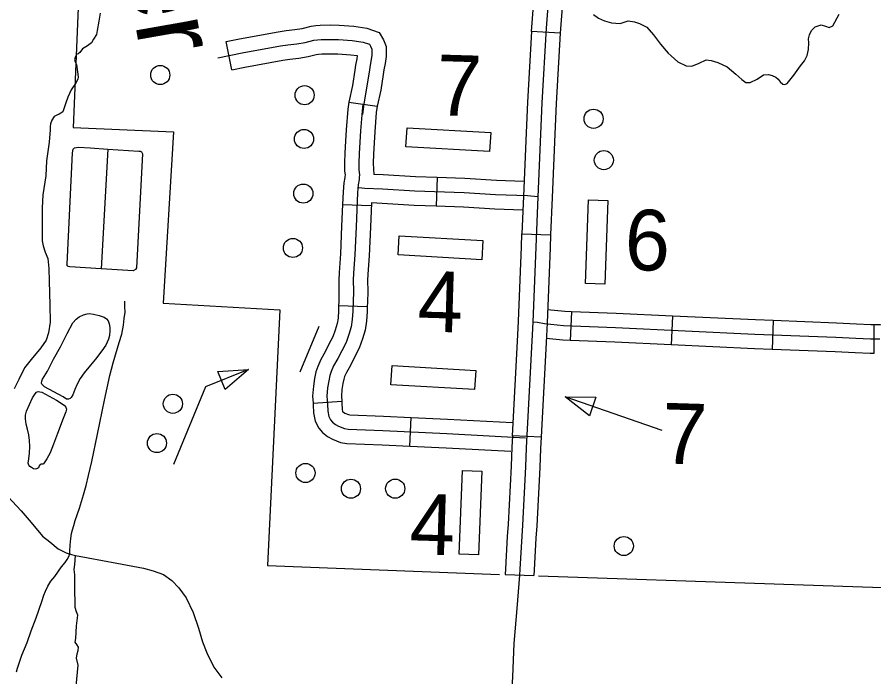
# Model space of a CAD drawing. Extents: x 653372 to 905732, y 627442 to 787275.
# Drawn here: x 690649 to 695124, y 780092 to 783537 of the extents above; entities that cross this region are included whole.
import ezdxf

# ---------------------------------------------------------------- set-up
doc = ezdxf.new("R2010")
doc.units = 0
for name, color, linetype in [('31', 7, 'Continuous'), ('32', 7, 'Continuous'), ('33', 7, 'Continuous'), ('34', 7, 'Continuous'), ('35', 7, 'Continuous'), ('45', 7, 'Continuous'), ('56', 7, 'Continuous'), ('6', 7, 'Continuous')]:
    doc.layers.add(name, color=color, linetype=linetype)

msp = doc.modelspace()

# ---------------------------------------------------------------- linework, layer by layer
at = {"layer": '31'}
for p, q in [((693485.5, 783452.3), (693335.8, 783461.2)), ((693285.4, 782404.8), (693435.3, 782399.2)), ((693435.3, 782399.2), (693435.3, 782399.2)), ((693385.4, 781343.3), (693235.6, 781351.1))]:
    msp.add_line(p, q, dxfattribs=at)
for points in [[(693335.8, 783461.2), (693337.2, 783484.8), (693345.3, 783596.8), (693348.1, 783659.5), (693349.8, 783717.8), (693358.7, 783986.7)], [(693508.6, 783981.7), (693499.8, 783713.1), (693498, 783653.9), (693495, 783588), (693486.9, 783475), (693485.5, 783452.3)], [(693420.2, 783592.4), (693412, 783479.9), (693388.9, 783088.9), (693367.8, 782598.5), (693357.8, 782334.8), (693341.8, 781944.7), (693307.4, 781288.1), (693303.4, 781188.1), (693287.7, 780884.5), (693274, 780653.3), (693273.2, 780623.2)], [(693335.8, 783461.2), (693314, 783092.8), (693307.1, 782932.8)], [(693485.5, 783452.3), (693463.8, 783085.1), (693457, 782926.3)], [(693307.1, 782932.8), (693292.8, 782601.5), (693285.4, 782404.8)], [(693457, 782926.3), (693442.7, 782595.4), (693435.3, 782399.2)], [(693263.2, 781878.4), (693266.9, 781948.2), (693282.8, 782337.8), (693285.4, 782404.8)], [(693435.3, 782399.2), (693432.7, 782331.9), (693416.7, 781941.2), (693413, 781870.5)], [(693235.6, 781351.1), (693263.2, 781878.4)], [(693413, 781870.5), (693385.4, 781343.3)], [(693235.6, 781351.1), (693232.5, 781291.5), (693228.5, 781191.5), (693212.8, 780888.6), (693209, 780824.3)], [(693385.4, 781343.3), (693382.3, 781284.6), (693378.4, 781184.7), (693362.6, 780880.3), (693358.7, 780815.4)], [(693209, 780824.3), (693199.1, 780656.6), (693198.2, 780625.8), (693348.1, 780620.5)], [(693358.7, 780815.4), (693349, 780650), (693348.1, 780620.5)]]:
    msp.add_lwpolyline(points, dxfattribs=at)
at = {"layer": '32'}
for p, q in [((692380.7, 783092), (692529.2, 783071)), ((692842.9, 782699.4), (692838.1, 782549.5)), ((692348.4, 782558.3), (692498.2, 782552.2)), ((692327.5, 782030.1), (692477.4, 782025.6)), ((693543.8, 781998.5), (693537.8, 781848.6)), ((694071.8, 781975.4), (694064.8, 781825.6)), ((694598.6, 781951.7), (694592.9, 781801.8)), ((695122.8, 781930.3), (695123.8, 781780.3)), ((692194.2, 781521.3), (692343.9, 781530.7)), ((692700.5, 781296.3), (692707.5, 781446.2))]:
    msp.add_line(p, q, dxfattribs=at)
for points in [[(692380.7, 783092), (692375.5, 783055.7), (692367.4, 782948.3), (692363.7, 782889.1), (692360, 782827.4), (692358.4, 782775.1), (692359.3, 782734.9), (692361.2, 782711.2), (692361, 782704.6), (692360.4, 782699.3), (692355.6, 782671.1), (692351, 782624.4), (692348.4, 782558.3)], [(692454.9, 783081.5), (692450.1, 783047.6), (692442.2, 782943.1), (692438.6, 782884.5), (692434.9, 782824), (692433.4, 782774.8), (692434.2, 782738.8), (692436.3, 782713.1), (692435.9, 782698.9), (692434.6, 782688.6), (692430, 782661.2), (692425.9, 782619.2), (692418.7, 782442.3), (692413.3, 782295.6), (692404.8, 782199.2), (692403.7, 782162.3), (692404.8, 782105.5), (692403.1, 782048.4), (692401.7, 782002), (692399.4, 781957.6), (692393.5, 781919.9), (692381, 781879.5), (692366.4, 781837.3), (692344.3, 781794.7), (692324.1, 781753.6), (692301.2, 781715.5), (692289, 781686.5), (692281.7, 781664.9), (692276.1, 781636.7), (692270.3, 781600.8), (692267.1, 781557.4), (692269.7, 781516.5), (692271.4, 781478.6), (692276.3, 781451.9), (692286.1, 781433.6), (692296.2, 781422), (692311, 781410.2), (692327.8, 781401.1), (692358.6, 781388.8), (692378.4, 781385.4), (692558.5, 781378.1), (692893.3, 781362.4), (693304.5, 781340.5)], [(692529.2, 783071), (692524.7, 783039.5), (692517.1, 782938), (692513.5, 782879.9), (692509.8, 782820.6), (692508.4, 782774.5), (692509.2, 782742.6), (692511.4, 782715.4)], [(692842.9, 782699.4), (692729.7, 782703.1), (692560.3, 782712.9), (692511.4, 782715.4)], [(693296.2, 782678.9), (693151.7, 782684.1), (692987.9, 782694.7), (692842.9, 782699.4)], [(693367.8, 782598.5), (693314.5, 782603.2), (693148, 782609.1), (692984.3, 782619.7), (692726.3, 782628.1), (692556.2, 782638), (692464.5, 782642.6), (692434.3, 782645.8)], [(692348.4, 782558.3), (692343.7, 782445.2), (692338.5, 782300.3), (692329.9, 782203.7), (692328.6, 782162.7), (692329.8, 782105.8), (692328.1, 782050.6), (692327.5, 782030.1)], [(692498.8, 782566.2), (692493.6, 782439.4), (692488.2, 782290.9), (692479.7, 782194.8), (692478.7, 782162), (692479.8, 782105.1), (692478, 782046.1), (692477.4, 782025.6)], [(692838.1, 782549.5), (692723, 782553.2), (692498.8, 782566.2)], [(693290.1, 782529), (693144.2, 782534.2), (692980.6, 782544.8), (692838.1, 782549.5)], [(692327.5, 782030.1), (692326.7, 782005.1), (692324.7, 781965.3), (692320.3, 781936.9), (692309.7, 781902.9), (692297.3, 781866.9), (692277.4, 781828.5), (692258.2, 781789.5), (692234.2, 781749.5), (692218.8, 781713.1), (692209.1, 781684.2), (692202.3, 781649.9), (692195.8, 781609.6), (692191.9, 781557.8), (692194.2, 781521.3)], [(692477.4, 782025.6), (692476.6, 781999), (692474.1, 781949.9), (692466.8, 781902.8), (692452.2, 781856.1), (692435.5, 781807.7), (692411.3, 781760.9), (692390.1, 781717.7), (692368.3, 781681.4), (692359.2, 781659.9), (692354.3, 781645.6), (692350, 781623.4), (692344.9, 781592.1), (692342.3, 781556.9), (692343.9, 781530.7)], [(693543.8, 781998.5), (693508.7, 781999.9), (693419.5, 782008.9)], [(694071.8, 781975.4), (693777.6, 781989.1), (693543.8, 781998.5)], [(694598.6, 781951.7), (694506, 781955.2), (694071.8, 781975.4)], [(694925, 781864.1), (694502.8, 781880.3), (693774.3, 781914.1), (693503.4, 781925.1), (693403.3, 781935.1), (693367, 781942.5), (693341.8, 781944.7)], [(695122.8, 781930.3), (695108.4, 781930.2), (695032.7, 781933.8), (694928.3, 781939.1), (694598.6, 781951.7)], [(695653.2, 781901.9), (695571, 781905), (695462.8, 781910.3), (695289.9, 781922.2), (695156.4, 781930.5), (695122.8, 781930.3)], [(693537.8, 781848.6), (693498.2, 781850.2), (693412.4, 781858.8)], [(694064.8, 781825.6), (693771.1, 781839.2), (693537.8, 781848.6)], [(695154.3, 781855.5), (695106.8, 781855.2), (695029, 781858.9), (694925, 781864.1)], [(694592.9, 781801.8), (694499.6, 781805.4), (694064.8, 781825.6)], [(695123.8, 781780.3), (695105.3, 781780.1), (695025.3, 781784), (694921.6, 781789.2), (694592.9, 781801.8)], [(692194.2, 781521.3), (692194.8, 781512.5), (692196.7, 781470.1), (692204.6, 781426.8), (692224, 781390.8), (692244, 781367.7), (692269.5, 781347.3), (692296, 781333), (692338.1, 781316.3), (692370.5, 781310.7), (692555.2, 781303.2), (692700.5, 781296.3)], [(692343.9, 781530.7), (692344.6, 781520.6), (692346.1, 781487.1), (692347.9, 781477.1), (692348.3, 781476.4), (692348.4, 781476.2), (692352.5, 781473), (692359.5, 781469.2), (692379.2, 781461.4), (692386.4, 781460.1), (692561.8, 781453), (692707.5, 781446.2)], [(692707.5, 781446.2), (692897, 781437.3), (693235.3, 781419.3)], [(692700.5, 781296.3), (692889.5, 781287.5), (693227.4, 781269.5)]]:
    msp.add_lwpolyline(points, dxfattribs=at)
at = {"layer": '33'}
msp.add_lwpolyline([(693273.2, 780623.2), (693259.1, 780449.1), (693242.6, 780266.5), (693236.9, 780092.5), (693228.4, 779975), (693218.4, 779734.2), (693195.3, 779324.1)], dxfattribs=at)
at = {"layer": '34'}
msp.add_lwpolyline([(690644.8, 780117.1), (690650.5, 780136.8), (690658.6, 780162.6), (690672.9, 780204.6), (690700.4, 780271.8), (690722.6, 780331.7), (690748.5, 780400.5), (690777.6, 780486), (690788.2, 780518.5), (690796.8, 780539.2), (690809.5, 780565.5), (690825, 780591.1), (690845, 780616.5), (690879.9, 780665.9), (690899.5, 780689.1), (690909.6, 780704.6), (690918, 780720.2), (690923, 780734.8), (690924, 780748.4), (690926, 780778.9), (690928.2, 780814), (690931.8, 780839.9), (690936.9, 780859.6), (690944.4, 780882.6), (690952, 780907.3), (690974.3, 780972.6), (690995.6, 781041.6), (691008.4, 781091.1), (691021.3, 781144), (691038.8, 781216.1), (691068.6, 781359.7), (691104.2, 781537), (691133, 781664.7), (691150.8, 781731.6), (691181.2, 781837.3), (691196.1, 781881.6), (691204.8, 781927.8), (691208.2, 781963.4), (691212, 781996.7), (691211.1, 782023.9), (691211.4, 782053.3)], dxfattribs=at)
at = {"layer": '35'}
for points in [[(691082.7, 783556.9), (691075.6, 783515.7), (691066.2, 783466.8), (691063.6, 783445.2), (691048.1, 783421.1), (691036.7, 783401.7), (691016.6, 783386.6), (690990.5, 783370.6), (690976.2, 783352.4), (690967.1, 783345.8), (690959.1, 783341.1), (690952.9, 783331.4), (690948.5, 783314.8), (690951.1, 783303.9), (690958.6, 783289.9), (690961.2, 783278), (690962.7, 783262.2), (690964.3, 783252.3), (690967.4, 783223.7), (690966.1, 783212.9), (690953.6, 783190.3), (690930, 783157.6), (690914.1, 783118.7), (690903.3, 783088.5), (690891.4, 783052.4), (690887.2, 783041.7), (690876.1, 783035.2), (690867.2, 783030.5), (690855.2, 783025), (690842.2, 783017.5), (690829.8, 782999.2), (690823.3, 782979.7), (690820.9, 782965), (690821.4, 782948.3), (690821.9, 782945.5)], [(693660.1, 783549.8), (693686.1, 783531), (693716.9, 783516.9), (693752.6, 783507.3), (693798.9, 783504), (693841, 783516.9), (693874, 783512.1), (693899.3, 783503.8), (693937.5, 783484.6), (693973.2, 783443.8), (694008.7, 783395.4), (694049, 783347.7), (694064.2, 783335.4), (694100.2, 783303.1), (694144.1, 783282.8), (694172.4, 783281), (694211.7, 783296), (694247.3, 783313.8), (694273.7, 783310.2), (694308.4, 783299.7), (694356.9, 783276.4), (694402.2, 783239.1), (694434.5, 783210.7), (694455.8, 783194.9), (694477.6, 783195.1), (694514.1, 783212), (694547.9, 783235.7), (694573.6, 783237.7), (694593.3, 783232.4), (694612, 783223.3), (694623.9, 783212.5), (694633.9, 783198), (694647.8, 783187.2), (694659.1, 783185), (694670.6, 783190.3), (694705.6, 783233.8), (694741.1, 783282.9), (694760.8, 783308.8), (694775.9, 783336.8), (694781.5, 783367.9), (694783.5, 783401.9), (694782.2, 783422.8), (694786.7, 783443.5), (694798.7, 783466.8), (694817.3, 783486.2), (694847.9, 783495.7), (694870.4, 783489.3), (694891.1, 783483), (694909.3, 783491), (694942.4, 783552.4)], [(690821.4, 782948.3), (690815.5, 782883.9), (690801.8, 782785.9), (690798.4, 782707.2), (690782.7, 782609.3), (690778.7, 782541.5), (690779.1, 782456.8), (690779.4, 782368.2), (690784.5, 782342.5), (690795.3, 782309.7), (690808.1, 782276.8), (690814.4, 782223.3), (690816.3, 782157.3), (690819.5, 782035.1), (690820.8, 781944.5), (690813.2, 781887.7), (690800.2, 781850.7), (690772.4, 781809.2), (690721.4, 781748.7), (690686.6, 781704.5), (690657.3, 781645.3), (690632.2, 781594.9)], [(691088, 782222.5), (690924.5, 782232), (690915.5, 782234.5), (690908.9, 782241.5), (690909, 782246.1), (690937.9, 782827.5), (690941.9, 782847.9), (690948.9, 782853.4), (690968.3, 782857.3), (691029.6, 782854.3), (691121.5, 782847)], [(691121.5, 782847), (691283.8, 782837.6), (691290.6, 782837.4), (691298.4, 782832.6), (691302.7, 782823.4), (691272.3, 782228.4), (691266.4, 782219.4), (691254.8, 782211.8), (691088, 782222.5)], [(691121.5, 782847), (691088, 782222.5)], [(690874.5, 781815.5), (690910.5, 781884.1), (690939.9, 781939.8), (690956.4, 781959.7), (690972.6, 781971.7), (690995.5, 781981.8), (691014.4, 781987.4), (691024.6, 781988.8), (691047.7, 781985.3), (691076.4, 781978.8), (691102.8, 781969.5), (691115.5, 781961.2), (691123.7, 781951.3), (691130.1, 781935.8), (691133.4, 781915.9), (691132.3, 781898.4), (691130.5, 781874.1), (691125.9, 781854.4), (691112.5, 781823.6), (691091.2, 781793.7), (691057.1, 781750.5)], [(691057.1, 781750.5), (691031.3, 781719), (690998.3, 781678.6), (690978.2, 781650.4), (690962.6, 781620.2), (690949.3, 781592.9), (690938.9, 781564.9), (690931.6, 781550.9), (690924.7, 781545.5), (690917.2, 781541.7), (690905.9, 781541.5), (690888.7, 781553.4), (690790.6, 781606.7), (690784, 781612.6), (690778, 781620.1), (690775.9, 781624.7), (690776.7, 781634.9), (690781, 781646.1), (690807.2, 781688.3), (690839.1, 781751.4), (690874.5, 781815.5)], [(690703.3, 781385.1), (690695.6, 781411.4), (690692.4, 781438.7), (690692.4, 781457.9), (690697, 781478.7), (690713.4, 781513.4), (690728, 781548.6), (690742.2, 781570.3), (690749.9, 781578.5), (690758.4, 781581.7), (690766.3, 781580.9), (690777.6, 781577.7), (690855, 781535.7), (690894.5, 781510.2), (690903.2, 781499.2), (690905.7, 781488.9), (690903, 781475.4), (690889.5, 781440.7), (690858.9, 781362.3)], [(690858.9, 781362.3), (690837.9, 781306.5), (690820.2, 781261.7), (690803.9, 781229.9), (690786.2, 781204.4), (690783.3, 781202.8), (690778.8, 781202.9), (690774.8, 781202.5), (690769.1, 781199.8), (690764.3, 781193.2), (690761.9, 781188.1), (690760.6, 781183.1), (690754.9, 781179.3), (690749.1, 781177.2), (690743.5, 781176.8), (690734.4, 781178.2), (690723.9, 781184.2), (690714.4, 781190.1), (690709, 781197.1), (690705.9, 781207.9), (690709.4, 781229.4), (690713.7, 781259.8), (690715.3, 781294.3), (690713.9, 781325.5), (690709.2, 781355.7), (690703.3, 781385.1)], [(690599.6, 781033), (690670.1, 780959), (690722.4, 780897.4), (690781.3, 780825.7), (690819.7, 780796), (690862.9, 780760.3), (690904.6, 780739.3), (690931.9, 780730.7), (690953.4, 780725.6), (691019.9, 780713.2), (691169.6, 780685.1), (691308.6, 780659.3), (691359.3, 780645)], [(690952, 779986.6), (690964.5, 780116.6), (690967.3, 780152.7), (690958.9, 780189.2), (690961.3, 780211.6), (690967.9, 780229.5), (690969.3, 780246.7), (690960.2, 780260.8), (690951.9, 780273.1), (690955.1, 780292), (690958, 780358.7), (690964.8, 780413.7), (690959.3, 780432), (690951.3, 780454.7), (690952.2, 780484), (690950.4, 780537.6), (690949.2, 780583.3), (690950.4, 780624.7), (690946, 780651.6), (690950.3, 780679.1), (690953.4, 780725.6)], [(691359.3, 780645), (691412.4, 780626.1), (691456.7, 780594.2), (691492.9, 780555.7), (691531.7, 780504.4), (691568.8, 780428.5), (691595.8, 780346), (691617.3, 780275.4), (691639.1, 780217.5), (691676.2, 780142.6), (691717.8, 780086.2)]]:
    msp.add_lwpolyline(points, dxfattribs=at)
at = {"layer": '45'}
msp.add_line((691770.1, 783262.3), (691741.1, 783409.4), dxfattribs=at)
for points in [[(691741.1, 783409.4), (691810.6, 783423.1), (692011.9, 783460.1), (692053.4, 783466.1), (692098.7, 783471.6), (692137.7, 783478), (692185.3, 783490), (692208, 783492.3)], [(692208, 783492.3), (692231.5, 783494.7), (692286.5, 783495.8), (692329.9, 783494.5), (692406.9, 783490), (692475.5, 783479.7), (692539.9, 783456.1), (692562.6, 783418.1), (692576.1, 783384.2), (692576.2, 783353.9), (692576.1, 783330.5), (692570.7, 783293.9), (692564.3, 783260.8), (692560.8, 783237.5), (692547.8, 783155), (692529.2, 783071)], [(691696.2, 783324.1), (691824.6, 783349.5), (692024.1, 783386), (692063.4, 783391.8), (692109.2, 783397.3), (692153, 783404.4), (692198.3, 783416), (692236.1, 783419.8), (692286.1, 783420.7), (692326.6, 783419.5), (692399.2, 783415.4), (692456.8, 783406.7), (692489.1, 783394.8), (692495.2, 783384.8), (692501.2, 783369.7), (692501.2, 783353.9), (692501.1, 783336.1), (692496.8, 783306.5), (692490.4, 783273.5), (692486.6, 783248.9), (692473.8, 783167.4), (692457.1, 783072.3), (692453.3, 783028.4)], [(691770.1, 783262.3), (691838.6, 783275.8), (692036.3, 783312), (692073.3, 783317.4), (692119.7, 783323.1), (692168.2, 783330.9), (692211.4, 783341.9), (692223.1, 783343.1)], [(692223.1, 783343.1), (692240.6, 783344.8), (692285.7, 783345.7), (692323.3, 783344.6), (692391.5, 783340.7), (692425.3, 783335.6), (692422.8, 783319.2), (692416.4, 783286.3), (692412.5, 783260.3), (692399.8, 783179.7), (692380.7, 783092)]]:
    msp.add_lwpolyline(points, dxfattribs=at)
at = {"layer": '56'}
for p, q in [((691696.9, 781687), (691857.8, 781696.8)), ((691734.9, 781592.3), (691696.9, 781687)), ((691857.8, 781696.8), (691734.9, 781592.3)), ((693638.5, 781455.2), (693510.5, 781553.2)), ((693510.5, 781553.2), (693671.7, 781551.6)), ((693671.7, 781551.6), (693638.5, 781455.2))]:
    msp.add_line(p, q, dxfattribs=at)
for points in [[(692679.7, 782859), (692685.4, 782958.9), (693122.2, 782934), (693116.5, 782834.2)], [(693633.6, 782583.4), (693733.6, 782579.7), (693717.6, 782142.5), (693617.7, 782146.1)], [(692638.6, 782294.8), (692644.3, 782394.6), (693081.1, 782369.8), (693075.4, 782270)], [(692601.3, 781616.9), (692607, 781716.7), (693043.8, 781691.9), (693038.1, 781592)], [(693057.7, 780728), (692957.7, 780732.1), (692975.5, 781169.2), (693075.4, 781165.2)]]:
    msp.add_lwpolyline(points, close=True, dxfattribs=at)
for points in [[(692224.5, 781921.2), (692125.5, 781682.6)], [(691857.8, 781696.8), (691632.8, 781606.2), (691464.6, 781200.6)], [(694017.3, 781378.5), (693510.5, 781553.2)]]:
    msp.add_lwpolyline(points, dxfattribs=at)
for centre in [(691396.2, 783234.5), (692150.2, 783129.1), (693659.7, 783006), (692147.2, 782900.6), (693713.2, 782790.1), (692143.4, 782615.3), (692089.2, 782331.4), (691462.2, 781517.7), (691378.8, 781312.4), (692154.7, 781156.4), (692392.2, 781074.1), (692623.5, 781074.5), (693817.5, 780774.7)]:
    msp.add_circle(centre, 50, dxfattribs=at)
at = {"layer": '6'}
for points in [[(691091.6, 786379.3), (691708.4, 786357.1), (691687, 786258.1), (691704.6, 786143.2), (691737.2, 785968.4), (691699.8, 785881), (691655.6, 785810.5), (691641.3, 785680.3), (691565.5, 785622.7), (691476.9, 785494.9), (691450.6, 785372.7), (691415.3, 785403.1), (691379.3, 785407.9), (691047.4, 785422.1), (691014.7, 784713.5), (690941.2, 782961.2), (691464.6, 782937.9), (691411.6, 782043.7), (692020.6, 782007.6), (691955.6, 780672.3), (693169, 780626.9)], [(693371.1, 780619.7), (695833.5, 780535.9)]]:
    msp.add_lwpolyline(points, dxfattribs=at)

# ---------------------------------------------------------------- texts
at = {"layer": '35'}
msp.add_text('Otter', height=422.4, rotation=279.9612, dxfattribs=at).set_placement((691079.4, 784557.8))
at = {"layer": '56'}
for s, p in [('7', (692834.7, 783025.2)), ('6', (693819.2, 782217.7)), ('4', (692737.8, 781896.4)), ('7', (694012.1, 781206.5)), ('4', (692695.9, 780733.3))]:
    msp.add_text(s, height=316.8, rotation=358.28, dxfattribs=at).set_placement(p)

doc.saveas('drawing.dxf')
